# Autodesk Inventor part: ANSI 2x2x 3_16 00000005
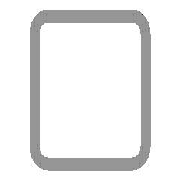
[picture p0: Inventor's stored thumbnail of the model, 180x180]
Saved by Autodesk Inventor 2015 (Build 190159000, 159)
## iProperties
_FrameMemberDoc: Frame Member File
_Version: 15.0.0
_CCFamilyMember: 1
_CCFamilyDisplayName: ANSI AISC (Square) - Tube
Created: 2007-02
Part Number: ANSI 2x2x 3_16 00000005
Material: Steel
Document SubType Name: Modeling
Standard: AISC
Designer: Autodesk, Inc.
Size Designation: 2x2x3/16
Stock Number: 2x2x 3/16
Density: 7.85 g/cm^3
Description: Tube
Standards Organization: ANSI
Language: en-US
Categories: <MemberInstance><Categories><Category DisplayName="Structural Shapes" InternalName="089c4875-fa83-4c05-b084-43b9cc11f5ed" Mnemonic="GRDR"><CategoryParameter Dis
Mass: 6278.25 g
Surface Area: 3375.01 cm^2
Volume: 799.777 cm^3
Appearance: Steel
IsCustomPart: 1
G_L: 38.465 in
G_W: 2.000 in
G_H: 2.000 in
+4286A8E8-304D-454A-A99C-8E0988DABACE+CUTDETAIL1: Cut
Author: Autodesk, Inc.
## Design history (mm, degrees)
node "Start plane"
node "End plane"
sketch "Sketch"
  geometry: L1 (-25.4, -15.875)-(-25.4, 15.875); L2 (-15.875, 25.4)-(15.875, 25.4); L3 (25.4, 15.875)-(25.4, -15.875); L4 (15.875, -25.4)-(-15.875, -25.4); L5 (-15.875, 20.637)-(15.875, 20.638); L6 (20.637, 15.875)-(20.637, -15.875); L7 (15.875, -20.637)-(-15.875, -20.638); L8 (-20.637, -15.875)-(-20.637, 15.875); L9 (0, 38.322)-(0, -38.322) reference; L10 (-38.322, 0)-(38.322, 0) reference; A1 r 9.525 centre (-15.875, -15.875) between (-25.4, -15.875) and (-15.875, -25.4); A2 r 9.525 centre (-15.875, 15.875) between (-15.875, 25.4) and (-25.4, 15.875); A3 r 9.525 centre (15.875, 15.875) between (25.4, 15.875) and (15.875, 25.4); A4 r 9.525 centre (15.875, -15.875) between (15.875, -25.4) and (25.4, -15.875); A5 r 4.762 centre (-15.875, 15.875) between (-15.875, 20.637) and (-20.637, 15.875); A6 r 4.762 centre (15.875, 15.875) between (20.637, 15.875) and (15.875, 20.638); A7 r 4.762 centre (15.875, -15.875) between (15.875, -20.637) and (20.637, -15.875); A8 r 4.762 centre (-15.875, -15.875) between (-20.637, -15.875) and (-15.875, -20.638)
  constraints: 16 end point, 16 point on circle, 8 centre point, 8 tangent, 4 parallel, 3 equal radius, 2 perpendicular, 7 other
  dimensions: "d10" = 50.8 distance between parallel lines of L2 L4 (= G_H); "d11" = 50.8 distance between parallel lines of L1 L3 (= G_W); "d12" = 4.7625 distance between parallel lines of L3 L6 (= G_T); "d15" = 25.4 distance between parallel lines of L2 L10 (= 0.5 x d10); "d16" = 25.4 distance between parallel lines of L9 L3 (= 0.5 x d11); "d17" = 9.525 radius of A1 (= G_IR)
extrude "Body" new body sketch "Sketch" stored distance "d3" = 977 (= G_L); taper "d4" = 0 deg
node "Driven Length"
  sketch "Sketch3"
    geometry: L1 (0, 0)-(10, 0) reference
    constraints: 2 end point, 1 horizontal
  workplane "Work Plane4"
  sketch "Sketch4"
    geometry: L1 (-2, -76.2)-(12, -76.2) reference; L2 (-2, 900.8)-(12, 900.8) reference
    dimensions: "d19" = 977 distance between parallel lines of L1 L2 (derived)
workplane "Work Plane3"
split "Split1"
body "Solid1"
other parameters: "G_W" = 50.8 [user parameter; used in 1 equation term], "G_H" = 50.8 [user parameter; used in 1 equation term], "G_T" = 4.7625 [user parameter; used in 1 equation term], "G_IR" = 9.525 [user parameter; used in 1 equation term], "G_L" = 977 (= d19) [user parameter; used in 1 equation term], "G_OFFSET_START" = 76.2 [user parameter; used in 1 equation term], "G_OFFSET_END" = 0 [user parameter; used in 1 equation term], "d13" = -76.2 (= -G_OFFSET_START), "d14" = 900.8 (= G_OFFSET_END + B_L), "B_L" = 900.8 [user parameter; used in 1 equation term], "d18" = 90 deg
